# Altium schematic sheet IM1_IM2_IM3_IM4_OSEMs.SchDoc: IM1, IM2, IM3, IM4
size C; Organization: LIGO Laboratory; Address1: California Institute of Technology; Address2: Massachusetts Institute of Technology; DocumentNumber: D0902810; Revision: v10; SheetNumber: 7; SheetTotal: 14; Engineer: J.Kissel/L.Sánchez
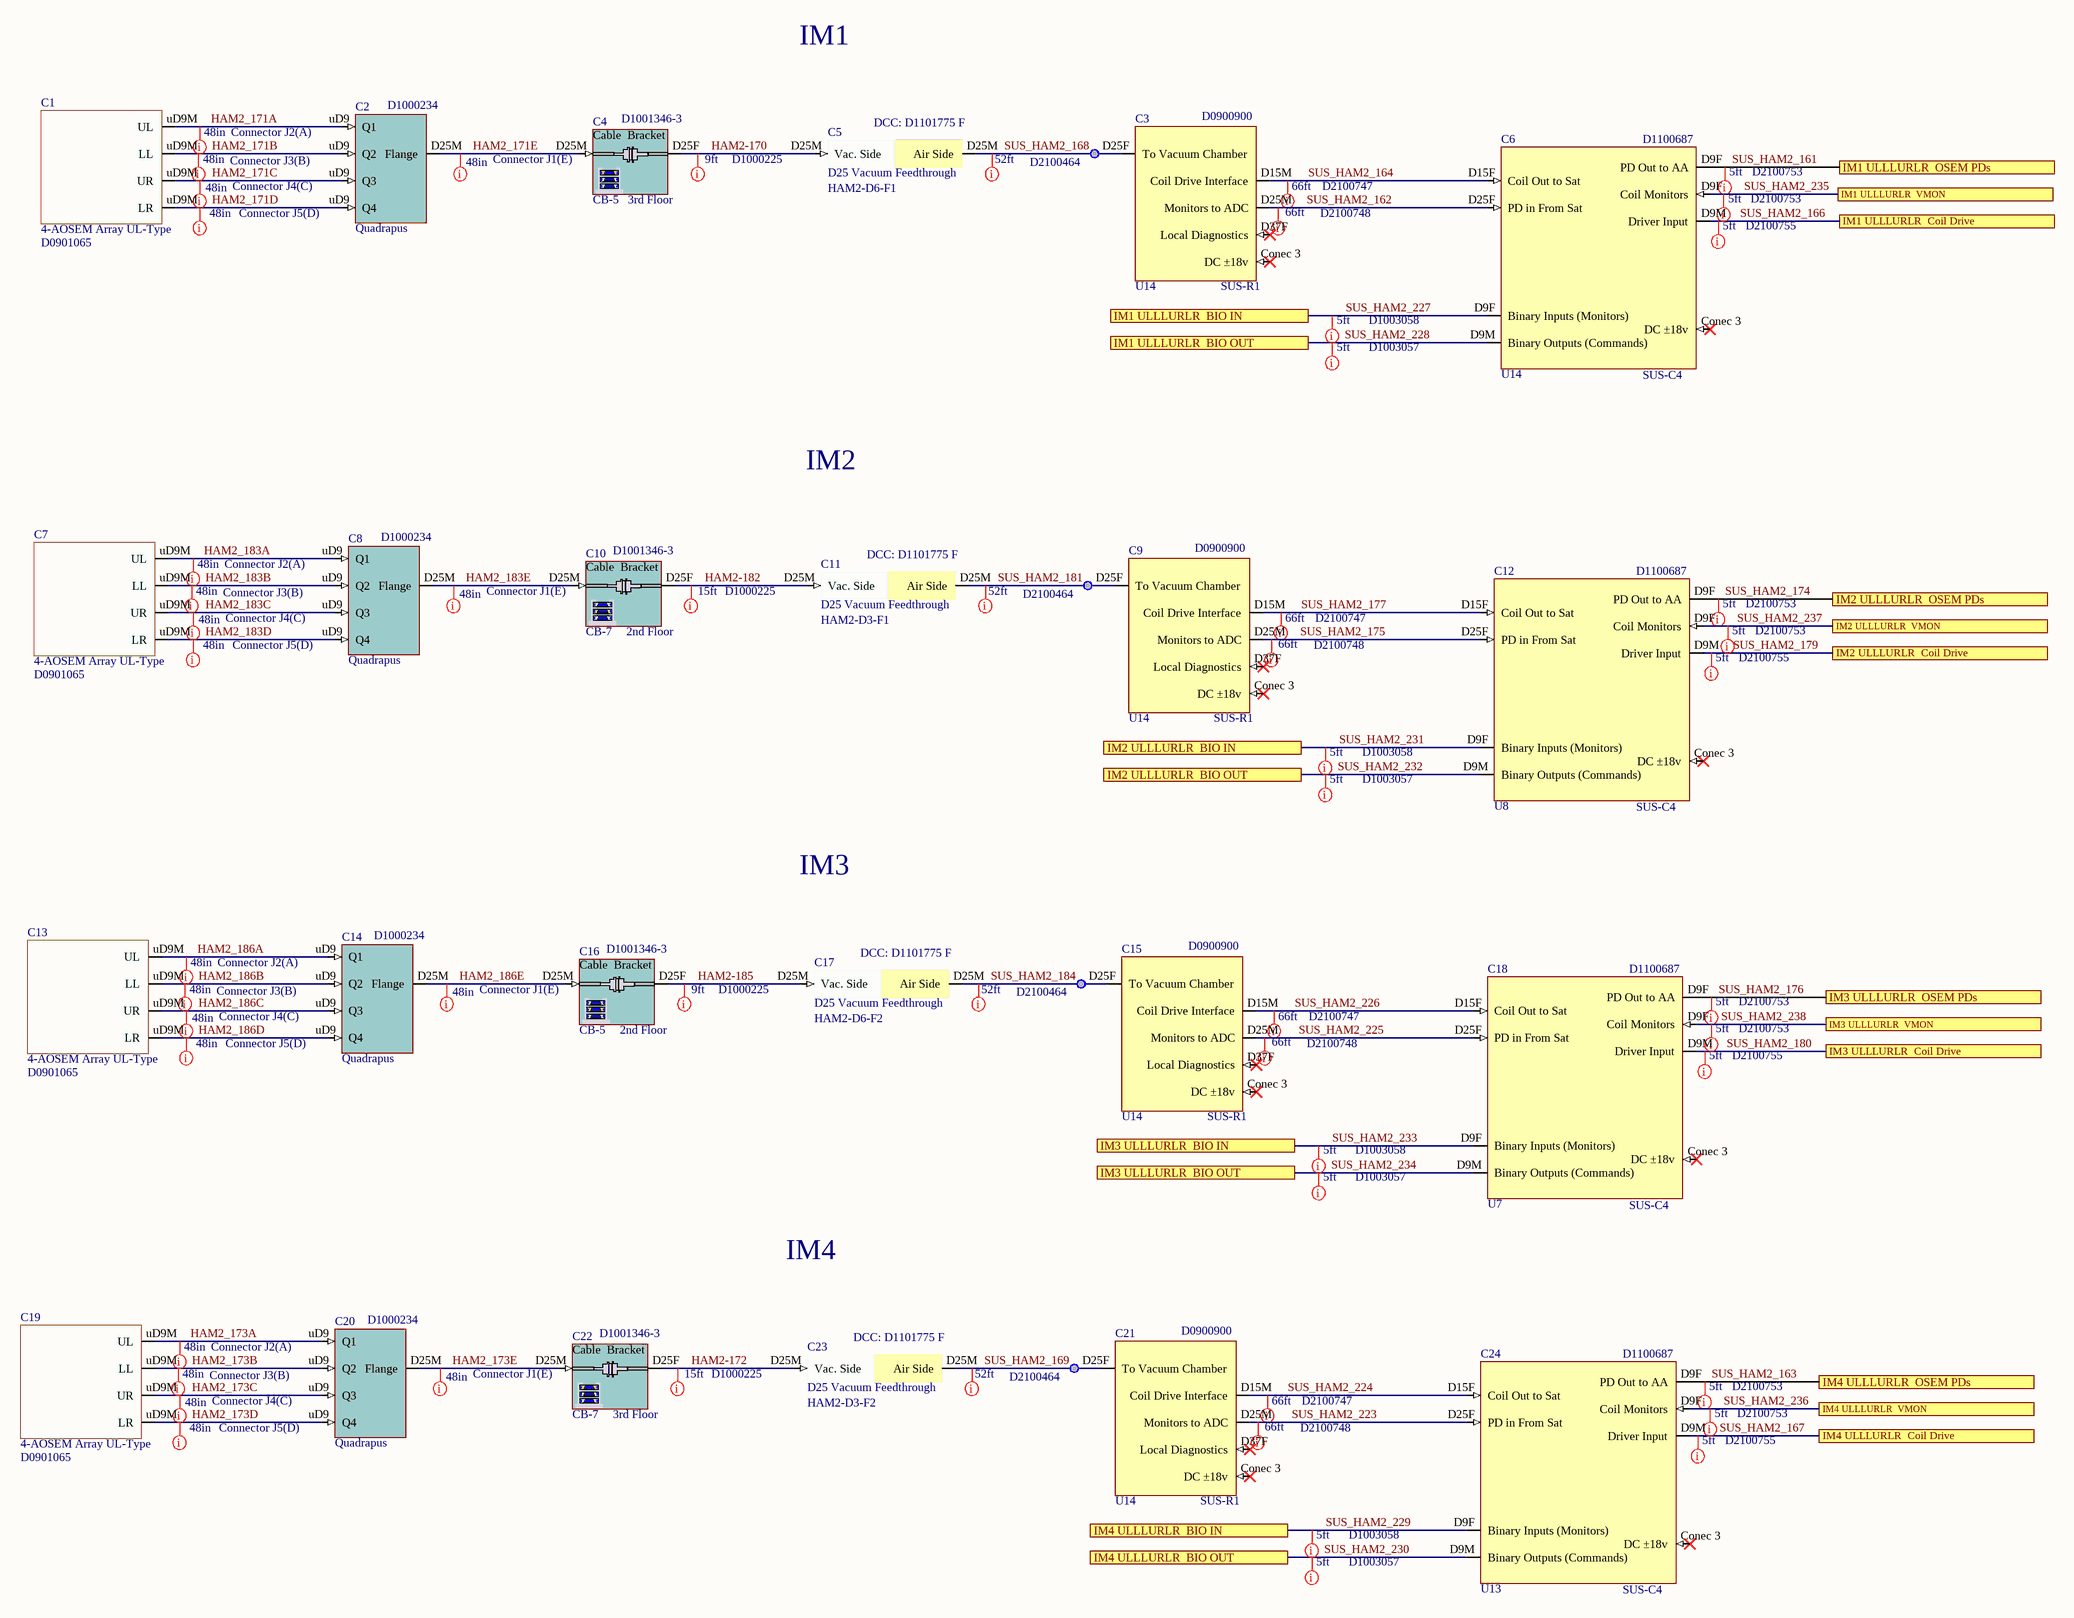
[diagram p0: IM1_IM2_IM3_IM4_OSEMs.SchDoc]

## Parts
C1  4-AOSEM Array UL-Type  DCC: D0901065
C2  Quadrapus  DCC: D1000234
C3  Slot: U14  Rack: SUS-R1  DCC: D0900900  (hidden comment: Satellite Amplifier UK D0900900)
C4  Rack: CB-5  DCC: D1001346-3  Slot: 3rd Floor  (hidden comment: D1001346-3 3rd Cable Bracket)
C5  D25 Vacuum Feedthrough  value HAM2-D6-F1  DCC: D1101775 F
C6  Slot: U14  Rack: SUS-C4  DCC: D1100687  (hidden comment: CD HAM-A D1100687)
C7  4-AOSEM Array UL-Type  DCC: D0901065
C8  Quadrapus  DCC: D1000234
C9  Slot: U14  Rack: SUS-R1  DCC: D0900900  (hidden comment: Satellite Amplifier UK D0900900)
C10  Rack: CB-7  DCC: D1001346-3  Slot: 2nd Floor  (hidden comment: D1001346-3 2nd Cable Bracket)
C11  D25 Vacuum Feedthrough  value HAM2-D3-F1  DCC: D1101775 F
C12  Slot: U8  Rack: SUS-C4  DCC: D1100687  (hidden comment: CD HAM-A D1100687)
C13  4-AOSEM Array UL-Type  DCC: D0901065
C14  Quadrapus  DCC: D1000234
C15  Slot: U14  Rack: SUS-R1  DCC: D0900900  (hidden comment: Satellite Amplifier UK D0900900)
C16  Rack: CB-5  DCC: D1001346-3  Slot: 2nd Floor  (hidden comment: D1001346-3 2nd Cable Bracket)
C17  D25 Vacuum Feedthrough  value HAM2-D6-F2  DCC: D1101775 F
C18  Slot: U7  Rack: SUS-C4  DCC: D1100687  (hidden comment: CD HAM-A D1100687)
C19  4-AOSEM Array UL-Type  DCC: D0901065
C20  Quadrapus  DCC: D1000234
C21  Slot: U14  Rack: SUS-R1  DCC: D0900900  (hidden comment: Satellite Amplifier UK D0900900)
C22  Rack: CB-7  DCC: D1001346-3  Slot: 3rd Floor  (hidden comment: D1001346-3 3rd Cable Bracket)
C23  D25 Vacuum Feedthrough  value HAM2-D3-F2  DCC: D1101775 F
C24  Slot: U13  Rack: SUS-C4  DCC: D1100687  (hidden comment: CD HAM-A D1100687)

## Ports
IM1 ULLLURLR  BIO IN, IM1 ULLLURLR  BIO OUT, IM1 ULLLURLR  Coil Drive, IM1 ULLLURLR  OSEM PDs, IM1 ULLLURLR  VMON, IM2 ULLLURLR  BIO IN, IM2 ULLLURLR  BIO OUT, IM2 ULLLURLR  Coil Drive, IM2 ULLLURLR  OSEM PDs, IM2 ULLLURLR  VMON, IM3 ULLLURLR  BIO IN, IM3 ULLLURLR  BIO OUT, IM3 ULLLURLR  Coil Drive, IM3 ULLLURLR  OSEM PDs, IM3 ULLLURLR  VMON, IM4 ULLLURLR  BIO IN, IM4 ULLLURLR  BIO OUT, IM4 ULLLURLR  Coil Drive, IM4 ULLLURLR  OSEM PDs, IM4 ULLLURLR  VMON

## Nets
HAM2-170: C4.D25F C5.D25M(Vac._Side)
HAM2-172: C22.D25F C23.D25M(Vac._Side)
HAM2-182: C10.D25F C11.D25M(Vac._Side)
HAM2-185: C16.D25F C17.D25M(Vac._Side)
HAM2_171A: C1.uD9M(UL) C2.uD9(Q1)
HAM2_171B: C1.uD9M(LL) C2.uD9(Q2)
HAM2_171C: C1.uD9M(UR) C2.uD9(Q3)
HAM2_171D: C1.uD9M(LR) C2.uD9(Q4)
HAM2_171E: C2.D25M(Flange) C4.D25M
HAM2_173A: C19.uD9M(UL) C20.uD9(Q1)
HAM2_173B: C19.uD9M(LL) C20.uD9(Q2)
HAM2_173C: C19.uD9M(UR) C20.uD9(Q3)
HAM2_173D: C19.uD9M(LR) C20.uD9(Q4)
HAM2_173E: C20.D25M(Flange) C22.D25M
HAM2_183A: C7.uD9M(UL) C8.uD9(Q1)
HAM2_183B: C7.uD9M(LL) C8.uD9(Q2)
HAM2_183C: C7.uD9M(UR) C8.uD9(Q3)
HAM2_183D: C7.uD9M(LR) C8.uD9(Q4)
HAM2_183E: C8.D25M(Flange) C10.D25M
HAM2_186A: C13.uD9M(UL) C14.uD9(Q1)
HAM2_186B: C13.uD9M(LL) C14.uD9(Q2)
HAM2_186C: C13.uD9M(UR) C14.uD9(Q3)
HAM2_186D: C13.uD9M(LR) C14.uD9(Q4)
HAM2_186E: C14.D25M(Flange) C16.D25M
SUS_HAM2_161: C6.D9F(PD_Out_to_AA) ; port IM1 ULLLURLR  OSEM PDs
SUS_HAM2_162: C3.D25M(Monitors_to_ADC) C6.D25F(PD_in_From_Sat)
SUS_HAM2_163: C24.D9F(PD_Out_to_AA) ; port IM4 ULLLURLR  OSEM PDs
SUS_HAM2_164: C3.D15M(Coil_Drive_Interface) C6.D15F(Coil_Out_to_Sat)
SUS_HAM2_166: C6.D9M(Driver_Input) ; port IM1 ULLLURLR  Coil Drive
SUS_HAM2_167: C24.D9M(Driver_Input) ; port IM4 ULLLURLR  Coil Drive
SUS_HAM2_168: C3.D25F(To_Vacuum_Chamber) C5.D25M(Air_Side)
SUS_HAM2_169: C21.D25F(To_Vacuum_Chamber) C23.D25M(Air_Side)
SUS_HAM2_174: C12.D9F(PD_Out_to_AA) ; port IM2 ULLLURLR  OSEM PDs
SUS_HAM2_175: C9.D25M(Monitors_to_ADC) C12.D25F(PD_in_From_Sat)
SUS_HAM2_176: C18.D9F(PD_Out_to_AA) ; port IM3 ULLLURLR  OSEM PDs
SUS_HAM2_177: C9.D15M(Coil_Drive_Interface) C12.D15F(Coil_Out_to_Sat)
SUS_HAM2_179: C12.D9M(Driver_Input) ; port IM2 ULLLURLR  Coil Drive
SUS_HAM2_180: C18.D9M(Driver_Input) ; port IM3 ULLLURLR  Coil Drive
SUS_HAM2_181: C9.D25F(To_Vacuum_Chamber) C11.D25M(Air_Side)
SUS_HAM2_184: C15.D25F(To_Vacuum_Chamber) C17.D25M(Air_Side)
SUS_HAM2_223: C21.D25M(Monitors_to_ADC) C24.D25F(PD_in_From_Sat)
SUS_HAM2_224: C21.D15M(Coil_Drive_Interface) C24.D15F(Coil_Out_to_Sat)
SUS_HAM2_225: C15.D25M(Monitors_to_ADC) C18.D25F(PD_in_From_Sat)
SUS_HAM2_226: C15.D15M(Coil_Drive_Interface) C18.D15F(Coil_Out_to_Sat)
SUS_HAM2_227: C6.D9F(Binary_Inputs_(Monitors)) ; port IM1 ULLLURLR  BIO IN
SUS_HAM2_228: C6.D9M(Binary_Outputs_(Commands)) ; port IM1 ULLLURLR  BIO OUT
SUS_HAM2_229: C24.D9F(Binary_Inputs_(Monitors)) ; port IM4 ULLLURLR  BIO IN
SUS_HAM2_230: C24.D9M(Binary_Outputs_(Commands)) ; port IM4 ULLLURLR  BIO OUT
SUS_HAM2_231: C12.D9F(Binary_Inputs_(Monitors)) ; port IM2 ULLLURLR  BIO IN
SUS_HAM2_232: C12.D9M(Binary_Outputs_(Commands)) ; port IM2 ULLLURLR  BIO OUT
SUS_HAM2_233: C18.D9F(Binary_Inputs_(Monitors)) ; port IM3 ULLLURLR  BIO IN
SUS_HAM2_234: C18.D9M(Binary_Outputs_(Commands)) ; port IM3 ULLLURLR  BIO OUT
SUS_HAM2_235: C6.D9F(Coil_Monitors) ; port IM1 ULLLURLR  VMON
SUS_HAM2_236: C24.D9F(Coil_Monitors) ; port IM4 ULLLURLR  VMON
SUS_HAM2_237: C12.D9F(Coil_Monitors) ; port IM2 ULLLURLR  VMON
SUS_HAM2_238: C18.D9F(Coil_Monitors) ; port IM3 ULLLURLR  VMON

Not connected (* = marked no-connect by the designer): C3 Conec 3(DC_±18v)* D37F(Local_Diagnostics)*; C6 Conec 3(DC_±18v)*; C9 Conec 3(DC_±18v)* D37F(Local_Diagnostics)*; C12 Conec 3(DC_±18v)*; C15 Conec 3(DC_±18v)* D37F(Local_Diagnostics)*; C18 Conec 3(DC_±18v)*; C21 Conec 3(DC_±18v)* D37F(Local_Diagnostics)*; C24 Conec 3(DC_±18v)*

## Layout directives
Length: 52ft; DCC: D2100464: SUS_HAM2_168, SUS_HAM2_169, SUS_HAM2_181, SUS_HAM2_184
Length: 5ft; DCC: D2100753: SUS_HAM2_161, SUS_HAM2_163, SUS_HAM2_174, SUS_HAM2_176, SUS_HAM2_235, SUS_HAM2_236, SUS_HAM2_237, SUS_HAM2_238
Length: 5ft; DCC: D2100755: SUS_HAM2_166, SUS_HAM2_167, SUS_HAM2_179, SUS_HAM2_180
Length: 48in; DCC: Connector J5(D): HAM2_171D, HAM2_173D, HAM2_183D, HAM2_186D
Length: 48in; DCC: Connector J4(C): HAM2_171C, HAM2_173C, HAM2_183C, HAM2_186C
Length: 48in; DCC: Connector J3(B): HAM2_171B, HAM2_173B, HAM2_183B, HAM2_186B
Length: 48in; DCC: Connector J2(A): HAM2_171A, HAM2_173A, HAM2_183A, HAM2_186A
Length: 66ft; DCC: D2100747: SUS_HAM2_164, SUS_HAM2_177, SUS_HAM2_224, SUS_HAM2_226
Length: 66ft; DCC: D2100748: SUS_HAM2_162, SUS_HAM2_175, SUS_HAM2_223, SUS_HAM2_225
Length: 5ft; DCC: D1003058: SUS_HAM2_227, SUS_HAM2_229, SUS_HAM2_231, SUS_HAM2_233
Length: 5ft; DCC: D1003057: SUS_HAM2_228, SUS_HAM2_230, SUS_HAM2_232, SUS_HAM2_234
Length: 48in; DCC: Connector J1(E): HAM2_171E, HAM2_173E, HAM2_183E, HAM2_186E
Length: 9ft; DCC: D1000225: HAM2-170, HAM2-185
Length: 15ft; DCC: D1000225: HAM2-172, HAM2-182

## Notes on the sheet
- IM1
- IM2
- IM3
- IM4

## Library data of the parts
C1 C7 C13 C19 = 4-AOSEM Array UL-Type: Rack: R?; Slot: U?; Serial: Sxxxxxxx; System: SUS
C2 C8 C14 C20 = D1000234 D25 Quadrapus: Slot: U?; Rack: R?; Serial: Sxxxxxxx; System: SUS
C3 C9 C15 C21 = Satellite Amplifier UK D0900900: System: SUS; Serial: Sxxxxxxx
C4 C22 = D1001346-3 3rd Cable Bracket: D1001346-3 3rd Cable Bracket for HAM Tables; Serial: Sxxxxxxx; System: SUS
C5 C11 C17 C23 = VacFeedD25: Serial: Sxxxxxxx; System: ISC; Rack: R?; Slot: U?
C6 C12 C18 C24 = CD HAM-A D1100687: System: SUS; Serial: Sxxxxxxx
C10 C16 = D1001346-3 2nd Cable Bracket: D1001346-3 2nd Cable Bracket  for HAM Tables; Serial: Sxxxxxxx; System: SUS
